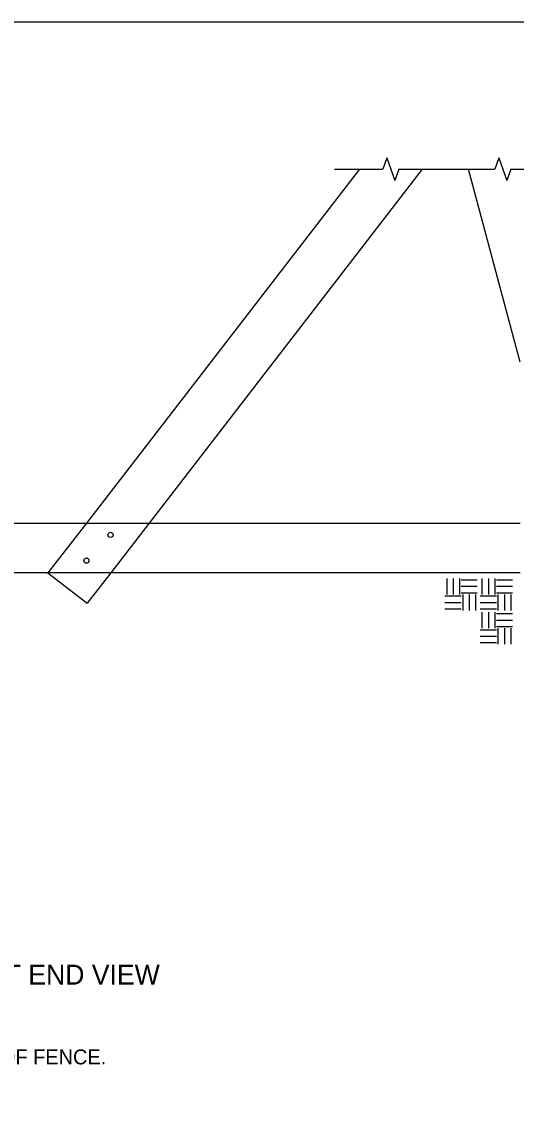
# Model space of a CAD drawing. Extents: x 49991.4 to 50021, y 49987.6 to 50011.4.
# Drawn here: x 50002.947 to 50004.937, y 49994.611 to 49998.999 of the extents above; entities that cross this region are included whole.
import ezdxf

# ---------------------------------------------------------------- set-up
doc = ezdxf.new("R2010")
doc.units = 0
for name, color, linetype in [('Level 1', 7, 'Continuous'), ('Level 2', 7, 'Continuous'), ('Level 4', 7, 'Continuous'), ('Level 6', 7, 'Continuous')]:
    doc.layers.add(name, color=color, linetype=linetype)

msp = doc.modelspace()

# ---------------------------------------------------------------- linework, layer by layer
at = {"layer": 'Level 1'}
for p, q in [((50004.3059, 49998.4062), (50003.2069, 49996.9838)), ((50004.5586, 49998.4062), (50003.4596, 49996.9838)), ((50004.9525, 49997.6307), (50004.7448, 49998.4062)), ((50001.0856, 49996.9838), (50004.9525, 49996.9838)), ((50004.9525, 49996.7838), (50000.2807, 49996.7838)), ((50003.0523, 49996.7838), (50003.2106, 49996.6614)), ((50003.3051, 49996.7838), (50003.2106, 49996.6614)), ((50004.6573, 49996.7613), (50004.6573, 49996.6965)), ((50004.6832, 49996.7613), (50004.6832, 49996.6965)), ((50004.7092, 49996.7613), (50004.7092, 49996.6965)), ((50004.7152, 49996.7553), (50004.78, 49996.7553)), ((50004.7152, 49996.7294), (50004.78, 49996.7294)), ((50004.7992, 49996.7613), (50004.7992, 49996.6965)), ((50004.8251, 49996.7613), (50004.8251, 49996.6965)), ((50004.8511, 49996.7613), (50004.8511, 49996.6965)), ((50004.8571, 49996.7553), (50004.9219, 49996.7553)), ((50004.8571, 49996.7294), (50004.9219, 49996.7294)), ((50004.6503, 49996.6905), (50004.7152, 49996.6905)), ((50004.7152, 49996.7034), (50004.78, 49996.7034)), ((50004.7217, 49996.6969), (50004.7217, 49996.6321)), ((50004.7476, 49996.6969), (50004.7476, 49996.6321)), ((50004.7736, 49996.6969), (50004.7736, 49996.6321)), ((50004.7922, 49996.6905), (50004.8571, 49996.6905)), ((50004.8571, 49996.7034), (50004.9219, 49996.7034)), ((50004.8636, 49996.6969), (50004.8636, 49996.6321)), ((50004.8895, 49996.6969), (50004.8895, 49996.6321)), ((50004.9155, 49996.6969), (50004.9155, 49996.6321)), ((50004.6503, 49996.6645), (50004.7152, 49996.6645)), ((50004.6503, 49996.6386), (50004.7152, 49996.6386)), ((50004.7922, 49996.6645), (50004.8571, 49996.6645)), ((50004.7922, 49996.6386), (50004.8571, 49996.6386)), ((50004.7992, 49996.6254), (50004.7992, 49996.5606)), ((50004.8251, 49996.6254), (50004.8251, 49996.5606)), ((50004.8511, 49996.6254), (50004.8511, 49996.5606)), ((50004.8571, 49996.6194), (50004.9219, 49996.6194)), ((50004.7922, 49996.5546), (50004.8571, 49996.5546)), ((50004.8571, 49996.5935), (50004.9219, 49996.5935)), ((50004.8571, 49996.5675), (50004.9219, 49996.5675)), ((50004.8636, 49996.561), (50004.8636, 49996.4962)), ((50004.8895, 49996.561), (50004.8895, 49996.4962)), ((50004.9155, 49996.561), (50004.9155, 49996.4962)), ((50004.7922, 49996.5286), (50004.8571, 49996.5286)), ((50004.7922, 49996.5027), (50004.8571, 49996.5027))]:
    msp.add_line(p, q, dxfattribs=at)
msp.add_lwpolyline([(49999.3835, 49998.9992), (50016.7501, 49998.9992), (50016.7501, 49987.7988), (49999.3835, 49987.7988)], close=True, dxfattribs=at)
for centre in [(50003.3043, 49996.9361), (50003.2071, 49996.8324)]:
    msp.add_circle(centre, 0.0104, dxfattribs=at)
at = {"layer": 'Level 4'}
for p, q in [((50003.2069, 49996.9838), (50003.0523, 49996.7838)), ((50003.4596, 49996.9838), (50003.3051, 49996.7838))]:
    msp.add_line(p, q, dxfattribs=at)
at = {"layer": 'Level 6'}
for p, q in [((50004.416, 49998.4519), (50004.3998, 49998.4062)), ((50004.416, 49998.4519), (50004.4322, 49998.4062)), ((50004.8666, 49998.4519), (50004.8504, 49998.4062)), ((50004.8666, 49998.4519), (50004.8828, 49998.4062)), ((50004.2059, 49998.4062), (50004.3998, 49998.4062)), ((50004.4322, 49998.4062), (50004.4484, 49998.3605)), ((50004.4646, 49998.4062), (50004.4484, 49998.3605)), ((50004.4646, 49998.4062), (50004.8504, 49998.4062)), ((50004.8828, 49998.4062), (50004.899, 49998.3605)), ((50004.9152, 49998.4062), (50004.899, 49998.3605)), ((50004.9152, 49998.4062), (50005.1207, 49998.4062))]:
    msp.add_line(p, q, dxfattribs=at)

# ---------------------------------------------------------------- texts
at = {"layer": 'Level 2'}
for s, height, p in [('LEFT END VIEW', 0.08, (50002.682, 49995.1276)), ('HOLES SHOWN IN DETAILS BELOW ARE FOR LEFT END OF FENCE.', 0.06, (50000.6745, 49994.8069))]:
    msp.add_text(s, height=height, dxfattribs=at).set_placement(p)

doc.saveas('drawing.dxf')
